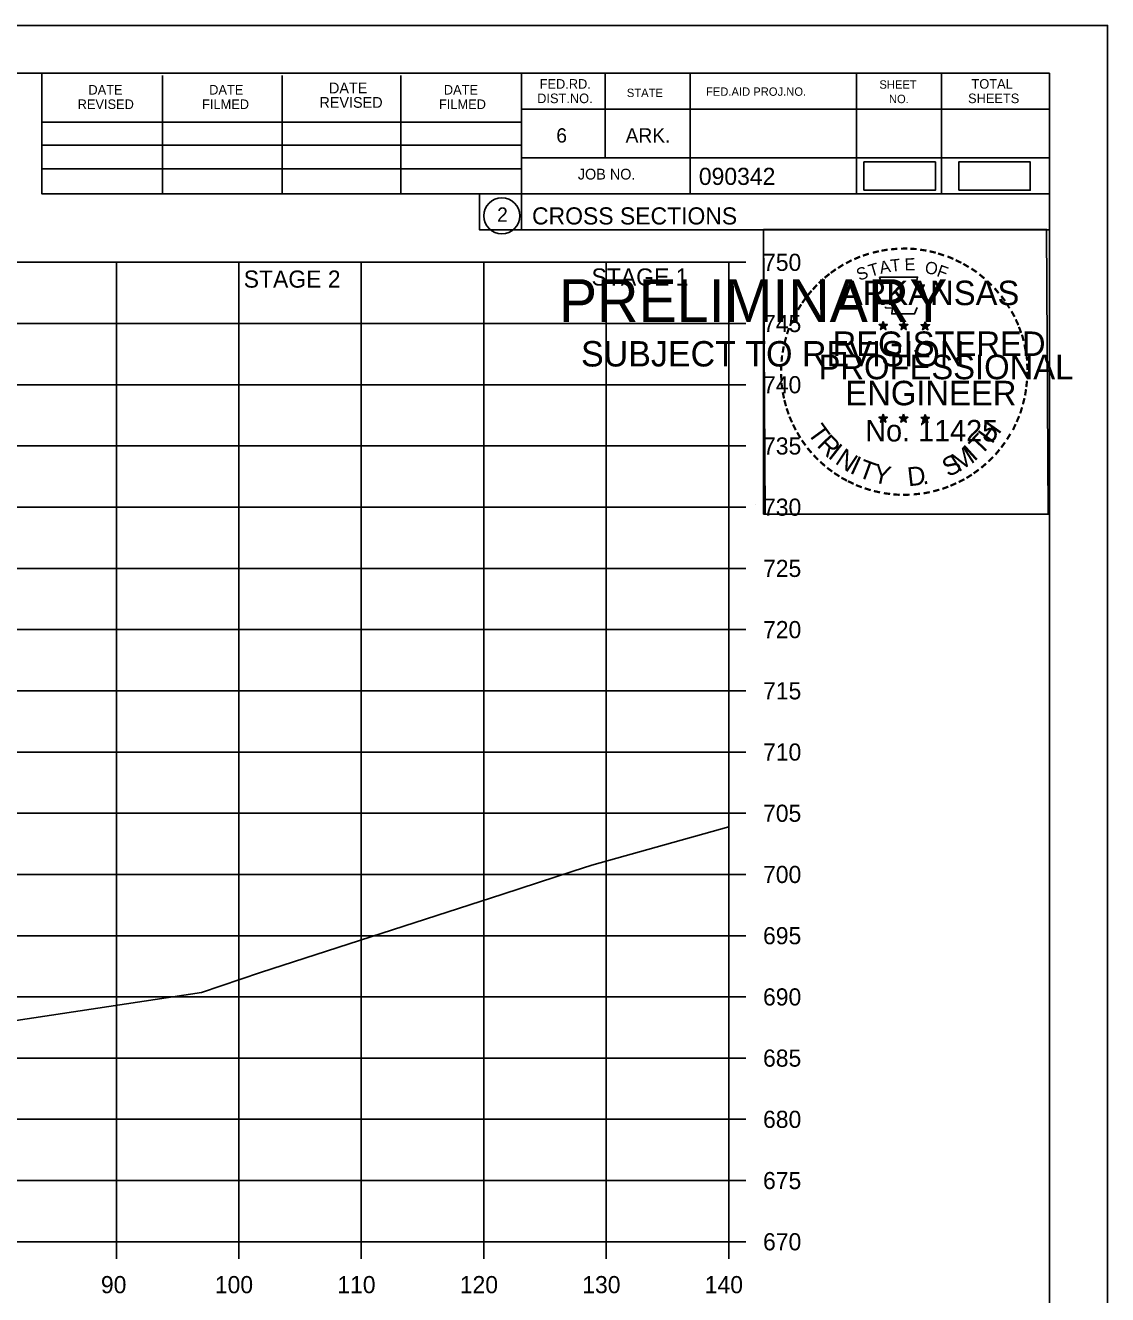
# Model space of a CAD drawing. Extents: x 1370515 to 1370849, y 383299 to 386073.
# Drawn here: x 1370760.4 to 1370848.7, y 383622.4 to 383726.1 of the extents above; entities that cross this region are included whole.
import ezdxf

# ---------------------------------------------------------------- set-up
doc = ezdxf.new("R2010")
doc.units = 0
for name, color, linetype in [('R_Axis', 7, 'Continuous'), ('R_Axis Annot', 7, 'Continuous'), ('R_Border', 7, 'Continuous'), ('R_Border PE', 7, 'Continuous'), ('R_Border Prem', 7, 'Continuous'), ('R_Detour', 7, 'Continuous'), ('R_Exist Surface', 7, 'Continuous'), ('R_Grid', 7, 'Continuous'), ('R_No Plot', 7, 'Continuous')]:
    doc.layers.add(name, color=color, linetype=linetype)

msp = doc.modelspace()

# ---------------------------------------------------------------- linework, layer by layer
at = {"layer": 'R_Axis'}
for p, q in [((1370819.2, 383706.75), (1370816.4, 383706.75)), ((1370817.8, 383626.75), (1370817.8, 383706.75)), ((1370819.2, 383701.75), (1370816.4, 383701.75)), ((1370819.2, 383696.75), (1370816.4, 383696.75)), ((1370819.2, 383691.75), (1370816.4, 383691.75)), ((1370819.2, 383686.75), (1370816.4, 383686.75)), ((1370819.2, 383681.75), (1370816.4, 383681.75)), ((1370819.2, 383676.75), (1370816.4, 383676.75)), ((1370819.2, 383671.75), (1370816.4, 383671.75)), ((1370819.2, 383666.75), (1370816.4, 383666.75)), ((1370819.2, 383661.75), (1370816.4, 383661.75)), ((1370819.2, 383656.75), (1370816.4, 383656.75)), ((1370819.2, 383651.75), (1370816.4, 383651.75)), ((1370819.2, 383646.75), (1370816.4, 383646.75)), ((1370819.2, 383641.75), (1370816.4, 383641.75)), ((1370819.2, 383636.75), (1370816.4, 383636.75)), ((1370819.2, 383631.75), (1370816.4, 383631.75)), ((1370767.8, 383625.35), (1370767.8, 383628.15)), ((1370777.8, 383625.35), (1370777.8, 383628.15)), ((1370787.8, 383625.35), (1370787.8, 383628.15)), ((1370797.8, 383625.35), (1370797.8, 383628.15)), ((1370807.8, 383625.35), (1370807.8, 383628.15)), ((1370817.8, 383625.35), (1370817.8, 383628.15)), ((1370537.8, 383626.75), (1370817.8, 383626.75)), ((1370819.2, 383626.75), (1370816.4, 383626.75))]:
    msp.add_line(p, q, dxfattribs=at)
at = {"layer": 'R_Border'}
for p, q in [((1370527.8, 383722.21), (1370843.98, 383722.21)), ((1370761.72, 383712.33), (1370761.72, 383722.21)), ((1370771.58, 383712.33), (1370771.58, 383722.01)), ((1370781.34, 383712.33), (1370781.34, 383722.01)), ((1370791.02, 383712.33), (1370791.02, 383722.01)), ((1370800.88, 383722.21), (1370800.88, 383709.41)), ((1370807.72, 383722.21), (1370807.72, 383715.27)), ((1370814.66, 383722.21), (1370814.66, 383712.33)), ((1370828.24, 383722.21), (1370828.24, 383712.33)), ((1370835.18, 383722.21), (1370835.18, 383712.33)), ((1370843.98, 383516.75), (1370843.98, 383722.21)), ((1370843.98, 383719.27), (1370800.88, 383719.27)), ((1370843.98, 383719.29), (1370843.98, 383719.29)), ((1370761.72, 383718.19), (1370800.88, 383718.19)), ((1370761.72, 383716.33), (1370800.88, 383716.33)), ((1370843.98, 383715.27), (1370800.88, 383715.27)), ((1370803.84, 383715.27), (1370843.98, 383715.27)), ((1370761.72, 383712.33), (1370761.72, 383714.39)), ((1370761.72, 383714.39), (1370800.88, 383714.39)), ((1370843.98, 383712.33), (1370761.72, 383712.33)), ((1370800.88, 383709.41), (1370843.98, 383709.41))]:
    msp.add_line(p, q, dxfattribs=at)
msp.add_circle((1370799.27, 383710.54), 1.47, dxfattribs=at)
at = {"layer": 'R_Border PE'}
for p, q in [((1370830.07, 383701.66), (1370830.42, 383701.55)), ((1370830.07, 383701.66), (1370830.32, 383701.62)), ((1370830.07, 383701.66), (1370830.3, 383701.54)), ((1370830.2, 383701.25), (1370830.42, 383701.55)), ((1370830.2, 383701.25), (1370830.33, 383701.5)), ((1370830.2, 383701.25), (1370830.41, 383701.47)), ((1370830.42, 383701.92), (1370830.37, 383701.66)), ((1370830.63, 383701.25), (1370830.41, 383701.47)), ((1370830.42, 383701.55), (1370830.42, 383701.92)), ((1370830.42, 383701.92), (1370830.46, 383701.67)), ((1370830.76, 383701.66), (1370830.42, 383701.55)), ((1370830.63, 383701.25), (1370830.42, 383701.55)), ((1370830.76, 383701.66), (1370830.48, 383701.61)), ((1370830.63, 383701.25), (1370830.49, 383701.54)), ((1370830.76, 383701.66), (1370830.56, 383701.56)), ((1370831.74, 383701.66), (1370832.09, 383701.55)), ((1370831.74, 383701.66), (1370831.99, 383701.62)), ((1370831.74, 383701.66), (1370831.97, 383701.54)), ((1370831.87, 383701.25), (1370832.09, 383701.55)), ((1370831.87, 383701.25), (1370832, 383701.5)), ((1370831.87, 383701.25), (1370832.08, 383701.47)), ((1370832.09, 383701.92), (1370832.04, 383701.66)), ((1370832.3, 383701.25), (1370832.08, 383701.47)), ((1370832.09, 383701.55), (1370832.09, 383701.92)), ((1370832.09, 383701.92), (1370832.13, 383701.67)), ((1370832.43, 383701.66), (1370832.09, 383701.55)), ((1370832.3, 383701.25), (1370832.09, 383701.55)), ((1370832.43, 383701.66), (1370832.15, 383701.61)), ((1370832.3, 383701.25), (1370832.16, 383701.54)), ((1370832.43, 383701.66), (1370832.23, 383701.56)), ((1370833.5, 383701.65), (1370833.85, 383701.54)), ((1370833.5, 383701.65), (1370833.75, 383701.6)), ((1370833.5, 383701.65), (1370833.74, 383701.53)), ((1370833.63, 383701.24), (1370833.85, 383701.54)), ((1370833.63, 383701.24), (1370833.76, 383701.49)), ((1370833.63, 383701.24), (1370833.85, 383701.46)), ((1370833.85, 383701.9), (1370833.81, 383701.65)), ((1370833.85, 383701.54), (1370833.85, 383701.9)), ((1370833.85, 383701.9), (1370833.9, 383701.65)), ((1370834.2, 383701.65), (1370833.85, 383701.54)), ((1370834.06, 383701.24), (1370833.85, 383701.54)), ((1370834.06, 383701.24), (1370833.85, 383701.46)), ((1370834.2, 383701.65), (1370833.91, 383701.6)), ((1370834.06, 383701.24), (1370833.93, 383701.53)), ((1370834.2, 383701.65), (1370833.99, 383701.55)), ((1370830.06, 383694.09), (1370830.41, 383693.98)), ((1370830.06, 383694.09), (1370830.32, 383694.04)), ((1370830.06, 383694.09), (1370830.3, 383693.97)), ((1370830.2, 383693.68), (1370830.41, 383693.98)), ((1370830.41, 383694.34), (1370830.37, 383694.09)), ((1370830.41, 383693.98), (1370830.41, 383694.34)), ((1370830.41, 383694.34), (1370830.46, 383694.09)), ((1370830.76, 383694.09), (1370830.41, 383693.98)), ((1370830.62, 383693.68), (1370830.41, 383693.98)), ((1370830.76, 383694.09), (1370830.47, 383694.04)), ((1370830.62, 383693.68), (1370830.49, 383693.97)), ((1370830.76, 383694.09), (1370830.55, 383693.99)), ((1370831.73, 383694.09), (1370832.08, 383693.98)), ((1370831.73, 383694.09), (1370831.98, 383694.04)), ((1370831.73, 383694.09), (1370831.97, 383693.97)), ((1370831.86, 383693.68), (1370832.08, 383693.98)), ((1370832.08, 383694.34), (1370832.04, 383694.09)), ((1370832.08, 383693.98), (1370832.08, 383694.34)), ((1370832.08, 383694.34), (1370832.13, 383694.09)), ((1370832.43, 383694.09), (1370832.08, 383693.98)), ((1370832.29, 383693.68), (1370832.08, 383693.98)), ((1370832.43, 383694.09), (1370832.14, 383694.04)), ((1370832.29, 383693.68), (1370832.16, 383693.97)), ((1370832.43, 383694.09), (1370832.22, 383693.99)), ((1370833.5, 383694.08), (1370833.85, 383693.97)), ((1370833.5, 383694.08), (1370833.75, 383694.03)), ((1370833.5, 383694.08), (1370833.74, 383693.96)), ((1370833.63, 383693.67), (1370833.85, 383693.97)), ((1370833.85, 383694.33), (1370833.81, 383694.08)), ((1370833.85, 383693.97), (1370833.85, 383694.33)), ((1370833.85, 383694.33), (1370833.9, 383694.08)), ((1370834.19, 383694.08), (1370833.85, 383693.97)), ((1370834.06, 383693.67), (1370833.85, 383693.97)), ((1370834.19, 383694.08), (1370833.91, 383694.03)), ((1370834.06, 383693.67), (1370833.92, 383693.96)), ((1370834.19, 383694.08), (1370833.99, 383693.98)), ((1370830.2, 383693.68), (1370830.32, 383693.92)), ((1370830.2, 383693.68), (1370830.41, 383693.9)), ((1370830.62, 383693.68), (1370830.41, 383693.89)), ((1370831.86, 383693.68), (1370831.99, 383693.92)), ((1370831.86, 383693.68), (1370832.08, 383693.9)), ((1370832.29, 383693.68), (1370832.08, 383693.89)), ((1370833.63, 383693.67), (1370833.76, 383693.91)), ((1370833.63, 383693.67), (1370833.85, 383693.89)), ((1370834.06, 383693.67), (1370833.85, 383693.88))]:
    msp.add_line(p, q, dxfattribs=at)
for points in [[(1370830.11, 383705.54), (1370830.38, 383704.71)], [(1370833.62, 383704.62), (1370833.76, 383704.9), (1370833.08, 383704.88), (1370833.22, 383705.54), (1370830.11, 383705.54)], [(1370830.6, 383703.12), (1370830.6, 383703.03), (1370831.16, 383703.01), (1370831.11, 383702.54), (1370832.98, 383702.54), (1370833.18, 383703.07)], [(1370830.42, 383701.92), (1370830.63, 383701.25), (1370830.07, 383701.66), (1370830.76, 383701.66), (1370830.2, 383701.25), (1370830.42, 383701.92)], [(1370832.09, 383701.92), (1370832.3, 383701.25), (1370831.74, 383701.66), (1370832.43, 383701.66), (1370831.87, 383701.25), (1370832.09, 383701.92)], [(1370833.85, 383701.9), (1370834.06, 383701.24), (1370833.5, 383701.65), (1370834.2, 383701.65), (1370833.63, 383701.24), (1370833.85, 383701.9)], [(1370830.41, 383694.34), (1370830.62, 383693.68), (1370830.06, 383694.09), (1370830.76, 383694.09), (1370830.2, 383693.68), (1370830.41, 383694.34)], [(1370832.08, 383694.34), (1370832.29, 383693.68), (1370831.73, 383694.09), (1370832.43, 383694.09), (1370831.86, 383693.68), (1370832.08, 383694.34)], [(1370833.85, 383694.33), (1370834.06, 383693.67), (1370833.5, 383694.08), (1370834.19, 383694.08), (1370833.63, 383693.67), (1370833.85, 383694.33)]]:
    msp.add_lwpolyline(points, dxfattribs=at)
for centre, radius in [((1370830.41, 383701.55), 0.172), ((1370830.41, 383701.55), 0.145), ((1370830.41, 383701.55), 0.116), ((1370830.41, 383701.55), 0.0991), ((1370830.41, 383701.55), 0.0747), ((1370830.41, 383701.55), 0.0495), ((1370830.41, 383701.55), 0.0296), ((1370832.08, 383701.55), 0.172), ((1370832.08, 383701.55), 0.145), ((1370832.08, 383701.55), 0.116), ((1370832.08, 383701.55), 0.0991), ((1370832.08, 383701.55), 0.0747), ((1370832.08, 383701.55), 0.0495), ((1370832.08, 383701.55), 0.0296), ((1370833.85, 383701.54), 0.172), ((1370833.85, 383701.54), 0.145), ((1370833.85, 383701.54), 0.116), ((1370833.85, 383701.54), 0.0991), ((1370833.85, 383701.54), 0.0747), ((1370833.85, 383701.54), 0.0495), ((1370833.85, 383701.54), 0.0296), ((1370830.41, 383693.98), 0.172), ((1370830.41, 383693.98), 0.145), ((1370830.41, 383693.98), 0.116), ((1370830.41, 383693.98), 0.0991), ((1370830.41, 383693.98), 0.0747), ((1370830.41, 383693.98), 0.0495), ((1370830.41, 383693.98), 0.0296), ((1370832.08, 383693.98), 0.172), ((1370832.08, 383693.98), 0.145), ((1370832.08, 383693.98), 0.116), ((1370832.08, 383693.98), 0.0991), ((1370832.08, 383693.98), 0.0747), ((1370832.08, 383693.98), 0.0495), ((1370832.08, 383693.98), 0.0296), ((1370833.85, 383693.97), 0.172), ((1370833.85, 383693.97), 0.145), ((1370833.85, 383693.97), 0.116), ((1370833.85, 383693.97), 0.0991), ((1370833.85, 383693.97), 0.0747), ((1370833.85, 383693.97), 0.0495), ((1370833.85, 383693.97), 0.0296)]:
    msp.add_circle(centre, radius, dxfattribs=at)
at = {"layer": 'R_Detour'}
for points in [[(1370828.84, 383712.64), (1370834.67, 383712.64), (1370834.67, 383714.95), (1370828.84, 383714.95)], [(1370836.58, 383712.64), (1370842.42, 383712.64), (1370842.42, 383714.95), (1370836.58, 383714.95)]]:
    msp.add_lwpolyline(points, close=True, dxfattribs=at)
at = {"layer": 'R_Exist Surface'}
msp.add_lwpolyline([(1370711.57, 383649.01), (1370723.09, 383646.26), (1370728.57, 383642.65), (1370731, 383641.06), (1370735.36, 383641.12), (1370738.15, 383641.23), (1370740.84, 383642.05), (1370743.68, 383642.77), (1370755.82, 383644.25), (1370774.74, 383647.12), (1370779.58, 383648.74), (1370799.35, 383655.15), (1370805.11, 383657.03), (1370806.63, 383657.52), (1370817.8, 383660.64)], dxfattribs=at)
at = {"layer": 'R_Grid'}
for p, q in [((1370537.8, 383706.75), (1370817.8, 383706.75)), ((1370767.8, 383626.75), (1370767.8, 383706.75)), ((1370777.8, 383626.75), (1370777.8, 383706.75)), ((1370787.8, 383626.75), (1370787.8, 383706.75)), ((1370797.8, 383626.75), (1370797.8, 383706.75)), ((1370807.8, 383626.75), (1370807.8, 383706.75)), ((1370817.8, 383626.75), (1370817.8, 383706.75)), ((1370537.8, 383701.75), (1370817.8, 383701.75)), ((1370537.8, 383696.75), (1370817.8, 383696.75)), ((1370537.8, 383691.75), (1370817.8, 383691.75)), ((1370537.8, 383686.75), (1370817.8, 383686.75)), ((1370537.8, 383681.75), (1370817.8, 383681.75)), ((1370537.8, 383676.75), (1370817.8, 383676.75)), ((1370537.8, 383671.75), (1370817.8, 383671.75)), ((1370537.8, 383666.75), (1370817.8, 383666.75)), ((1370537.8, 383661.75), (1370817.8, 383661.75)), ((1370537.8, 383656.75), (1370817.8, 383656.75)), ((1370537.8, 383651.75), (1370817.8, 383651.75)), ((1370537.8, 383646.75), (1370817.8, 383646.75)), ((1370537.8, 383641.75), (1370817.8, 383641.75)), ((1370537.8, 383636.75), (1370817.8, 383636.75)), ((1370537.8, 383631.75), (1370817.8, 383631.75)), ((1370537.8, 383626.75), (1370817.8, 383626.75))]:
    msp.add_line(p, q, dxfattribs=at)
at = {"layer": 'R_No Plot'}
for p, q in [((1370515.4, 383726.1), (1370848.73, 383726.1)), ((1370820.02, 383686.95), (1370820.02, 383686.95))]:
    msp.add_line(p, q, dxfattribs=at)
for points in [[(1370515.39, 383726.1), (1370848.73, 383726.1), (1370848.73, 383512.76), (1370515.39, 383512.76)], [(1370761.72, 383722.21), (1370761.72, 383712.33), (1370797.45, 383712.33), (1370797.45, 383709.41), (1370820.65, 383709.41), (1370820.65, 383686.19), (1370843.98, 383686.19), (1370843.98, 383516.75), (1370527.8, 383516.75), (1370527.8, 383722.21)], [(1370820.65, 383709.44), (1370843.75, 383709.44), (1370843.87, 383686.19), (1370820.77, 383686.19)]]:
    msp.add_lwpolyline(points, close=True, dxfattribs=at)

# ---------------------------------------------------------------- texts
at = {"layer": 'R_Axis Annot'}
for s, p in [('750', (1370820.6, 383706.05)), ('STAGE 2', (1370778.2, 383704.68)), ('STAGE 1', (1370806.6, 383704.85)), ('745', (1370820.6, 383701.05)), ('740', (1370820.6, 383696.05)), ('735', (1370820.6, 383691.05)), ('730', (1370820.6, 383686.05)), ('725', (1370820.6, 383681.05)), ('720', (1370820.6, 383676.05)), ('715', (1370820.6, 383671.05)), ('710', (1370820.6, 383666.05)), ('705', (1370820.6, 383661.05)), ('700', (1370820.6, 383656.05)), ('695', (1370820.6, 383651.05)), ('690', (1370820.6, 383646.05)), ('685', (1370820.6, 383641.05)), ('680', (1370820.6, 383636.05)), ('675', (1370820.6, 383631.05)), ('670', (1370820.6, 383626.05)), ('90', (1370766.54, 383622.55)), ('100', (1370775.84, 383622.55)), ('110', (1370785.84, 383622.55)), ('120', (1370795.84, 383622.55)), ('130', (1370805.84, 383622.55)), ('140', (1370815.84, 383622.55))]:
    msp.add_text(s, height=1.4, dxfattribs=at).set_placement(p)
at = {"layer": 'R_Border'}
for s, height, p in [('DATE', 0.782, (1370765.52, 383720.45)), ('DATE', 0.782, (1370775.38, 383720.45)), ('DATE', 0.879, (1370785.16, 383720.55)), ('DATE', 0.782, (1370794.54, 383720.45)), ('FED.RD.', 0.782, (1370802.36, 383720.93)), ('STATE', 0.684, (1370809.48, 383720.25)), ('FED.AID PROJ.NO.', 0.684, (1370815.94, 383720.35)), ('SHEET', 0.684, (1370830.1, 383720.93)), ('TOTAL', 0.782, (1370837.62, 383720.93)), ('REVISED', 0.782, (1370764.64, 383719.27)), ('FILMED', 0.782, (1370774.8, 383719.27)), ('REVISED', 0.879, (1370784.38, 383719.37)), ('FILMED', 0.782, (1370794.14, 383719.27)), ('DIST.NO.', 0.782, (1370802.16, 383719.75)), ('NO.', 0.684, (1370830.88, 383719.75)), ('SHEETS', 0.782, (1370837.34, 383719.75)), ('6', 1.17, (1370803.72, 383716.53)), ('ARK.', 1.172, (1370809.38, 383716.53)), ('JOB NO.', 0.879, (1370805.48, 383713.51)), ('090342', 1.4, (1370815.36, 383713.07)), ('2', 1.17, (1370798.89, 383710.06)), ('CROSS SECTIONS', 1.4, (1370801.74, 383709.84))]:
    msp.add_text(s, height=height, rotation=360, dxfattribs=at).set_placement(p)
at = {"layer": 'R_Border PE'}
for s, height, rotation, p in [('-', 1.6, 19.1761, (1370828.86, 383706.67)), ('-', 1.6, 13.6301, (1370829.61, 383706.91)), ('-', 1.6, 10.2193, (1370830.28, 383707.07)), ('-', 1.6, 5.8968, (1370831.01, 383707.18)), ('-', 1.6, 0.1862, (1370831.78, 383707.25)), ('-', 1.6, 357.743, (1370832.51, 383707.24)), ('-', 1.6, 352.1617, (1370833.25, 383707.18)), ('-', 1.6, 347.2049, (1370833.97, 383707.07)), ('-', 1.6, 342.3362, (1370834.61, 383706.91)), ('-', 1.6, 34.0636, (1370826.99, 383705.71)), ('-', 1.6, 28.7918, (1370827.59, 383706.08)), ('-', 1.6, 24.3072, (1370828.22, 383706.4)), ('T', 1, 16.4036, (1370829.38, 383705.55)), ('A', 1, 11.2132, (1370830.2, 383705.8)), ('T', 1, 6.0228, (1370831.05, 383705.97)), ('E', 1, 0.8323, (1370832.16, 383706.08)), ('O', 1, 350.4515, (1370833.76, 383705.87)), ('F', 1, 340.0707, (1370834.71, 383705.64)), ('-', 1.6, 337.8551, (1370835.34, 383706.69)), ('-', 1.6, 334.1211, (1370835.97, 383706.42)), ('-', 1.6, 329.6409, (1370836.55, 383706.14)), ('-', 1.6, 42.9622, (1370825.5, 383704.52)), ('-', 1.6, 38.9507, (1370825.94, 383704.94)), ('-', 1.6, 36.2317, (1370826.41, 383705.32)), ('S', 1, 21.594, (1370828.46, 383705.22)), ('-', 1.6, 325.8627, (1370837.19, 383705.78)), ('-', 1.6, 320.5297, (1370837.8, 383705.35)), ('-', 1.6, 50.6142, (1370824.65, 383703.56)), ('-', 1.6, 48.423, (1370825.06, 383704.04)), ('ARKANSAS', 2, 360, (1370826.96, 383703.25)), ('-', 1.6, 315.5786, (1370838.4, 383704.86)), ('-', 1.6, 309.8797, (1370838.97, 383704.31)), ('-', 1.6, 58.0706, (1370823.92, 383702.46)), ('-', 1.6, 54.2325, (1370824.24, 383702.99)), ('-', 1.6, 306.6522, (1370839.5, 383703.71)), ('-', 1.4, 303.6753, (1370839.98, 383703.14)), ('-', 1.6, 62.8713, (1370823.6, 383701.85)), ('-', 1.6, 299.6684, (1370840.3, 383702.53)), ('-', 1.6, 72.3945, (1370823.12, 383700.61)), ('-', 1.6, 67.7743, (1370823.34, 383701.24)), ('DWB', 0.01, 360, (1370830.4, 383701.55)), ('DWB', 0.01, 360, (1370832.07, 383701.55)), ('DWB', 0.01, 360, (1370833.84, 383701.53)), ('-', 1.6, 294.6628, (1370840.63, 383701.92)), ('-', 1.6, 290.5728, (1370840.88, 383701.35)), ('-', 1.6, 75.461, (1370822.93, 383699.89)), ('REGISTERED', 2, 360, (1370826.28, 383699.1)), ('-', 1.6, 285.1233, (1370841.12, 383700.77)), ('-', 1.6, 85.1863, (1370822.72, 383698.49)), ('-', 1.6, 81.2013, (1370822.8, 383699.18)), ('PROFESSIONAL', 2, 360, (1370825.13, 383697.2)), ('-', 1.6, 280.5493, (1370841.32, 383700.02)), ('-', 1.6, 276.5962, (1370841.48, 383699.26)), ('-', 1.6, 89.0622, (1370822.69, 383697.79)), ('-', 1.6, 274.3301, (1370841.54, 383698.53)), ('-', 1.6, 94.1959, (1370822.73, 383697.06)), ('ENGINEER', 2, 360, (1370827.32, 383695.07)), ('-', 1.6, 263.5172, (1370841.55, 383697.24)), ('-', 1.6, 269.9407, (1370841.57, 383697.9)), ('-', 1.6, 98.9479, (1370822.8, 383696.4)), ('-', 1.6, 101.7149, (1370822.94, 383695.66)), ('-', 1.6, 260.9953, (1370841.48, 383696.58)), ('-', 1.6, 105.4578, (1370823.1, 383695.07)), ('-', 1.6, 255.7626, (1370841.37, 383695.9)), ('-', 1.6, 109.0874, (1370823.31, 383694.44)), ('-', 1.6, 114.0643, (1370823.57, 383693.84)), ('DWB', 0.01, 360, (1370830.4, 383693.97)), ('DWB', 0.01, 360, (1370832.07, 383693.97)), ('DWB', 0.01, 360, (1370833.83, 383693.96)), ('-', 1.6, 247.8887, (1370840.97, 383694.51)), ('-', 1.6, 252.8681, (1370841.19, 383695.18)), ('-', 1.6, 115.7288, (1370823.87, 383693.22)), ('T', 1.54, 306.0406, (1370824.17, 383692.82)), ('No. 11425', 1.757, 360, (1370828.95, 383692.12)), ('H', 1.54, 54.6088, (1370839.29, 383691.85)), ('-', 1.6, 244.6197, (1370840.71, 383693.88)), ('-', 1.6, 120.4471, (1370824.23, 383692.64)), ('-', 1.6, 125.8934, (1370824.63, 383692.08)), ('R', 1.54, 314.005, (1370824.93, 383691.77)), ('I', 1.54, 321.9694, (1370825.83, 383690.84)), ('T', 1.54, 46.6444, (1370838.4, 383690.91)), ('-', 1.6, 233.8452, (1370839.91, 383692.48)), ('-', 1.6, 239.0712, (1370840.31, 383693.13)), ('-', 1.6, 130.7181, (1370825.09, 383691.52)), ('-', 1.6, 134.2238, (1370825.61, 383690.98)), ('N', 1.54, 326.5002, (1370826.4, 383690.36)), ('I', 1.54, 335.3603, (1370827.61, 383689.58)), ('S', 1.54, 26.9312, (1370835.72, 383689.18)), ('M', 1.54, 32.6563, (1370836.56, 383689.58)), ('I', 1.54, 42.1136, (1370837.84, 383690.43)), ('-', 1.6, 225.7653, (1370839, 383691.35)), ('-', 1.6, 231.2538, (1370839.48, 383691.91)), ('-', 1.6, 138.9338, (1370826.14, 383690.52)), ('-', 1.6, 144.6463, (1370826.69, 383690.11)), ('T', 1.54, 339.8912, (1370828.27, 383689.25)), ('Y', 1.54, 347.8556, (1370829.49, 383688.81)), ('D', 1.54, 6.3969, (1370832.47, 383688.45)), ('-', 1.6, 215.7363, (1370837.93, 383690.37)), ('-', 1.6, 221.0851, (1370838.48, 383690.84)), ('-', 1.6, 148.0898, (1370827.25, 383689.74)), ('-', 1.6, 151.5704, (1370827.83, 383689.41)), ('-', 1.6, 154.6002, (1370828.35, 383689.17)), ('.', 1.54, 13.7642, (1370833.66, 383688.57)), ('-', 1.6, 204.2516, (1370836.21, 383689.31)), ('-', 1.6, 207.3568, (1370836.84, 383689.63)), ('-', 1.6, 212.2491, (1370837.4, 383689.98)), ('-', 1.6, 158.5612, (1370828.98, 383688.91)), ('-', 1.6, 162.7983, (1370829.67, 383688.7)), ('-', 1.6, 167.5555, (1370830.38, 383688.54)), ('-', 1.6, 173.1155, (1370831.15, 383688.43)), ('-', 1.6, 176.5183, (1370831.9, 383688.37)), ('-', 1.6, 181.5918, (1370832.64, 383688.39)), ('-', 1.6, 185.8167, (1370833.45, 383688.47)), ('-', 1.6, 191.2858, (1370834.19, 383688.6)), ('-', 1.6, 195.4743, (1370834.92, 383688.8)), ('-', 1.6, 200.7184, (1370835.6, 383689.04))]:
    msp.add_text(s, height=height, rotation=rotation, dxfattribs=at).set_placement(p)
at = {"layer": 'R_Border Prem'}
for s, height, p in [('PRELIMINARY', 3.5, (1370803.93, 383701.87)), ('DWB', 0.01, (1370804.68, 383703.72)), ('SUBJECT TO REVISION', 2.0751, (1370805.74, 383698.24))]:
    msp.add_text(s, height=height, rotation=360, dxfattribs=at).set_placement(p)
at = {"layer": 'R_No Plot'}
for p in [(1370806.59, 383657.47), (1370774.69, 383647.07)]:
    msp.add_text('+', height=0.1, dxfattribs=at).set_placement(p)

doc.saveas('drawing.dxf')
